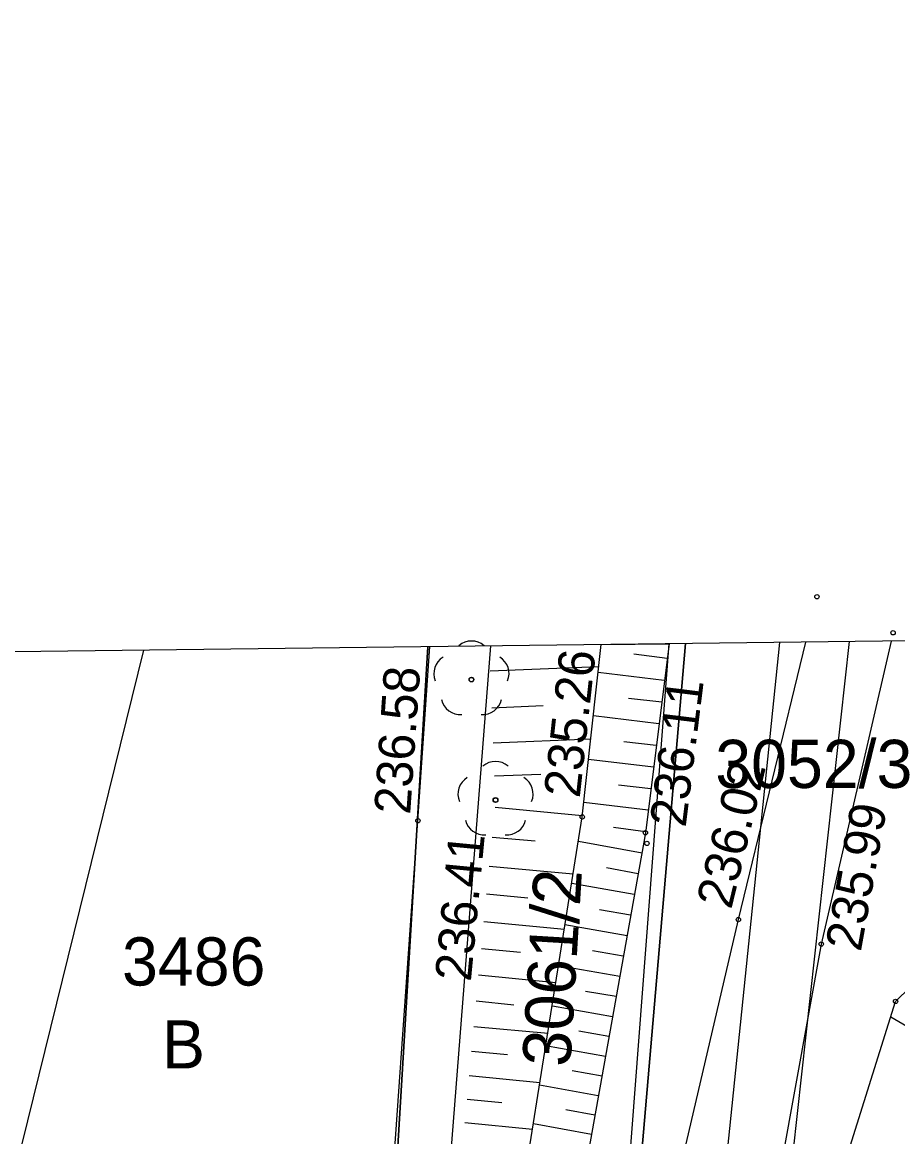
# Model space of a CAD drawing. Extents: x 6596400 to 6597200, y 5539751 to 5540251.
# Drawn here: x 6596707.49 to 6596725.66, y 5540110.79 to 5540133.92 of the extents above; entities that cross this region are included whole.
import ezdxf

# ---------------------------------------------------------------- set-up
doc = ezdxf.new("R2010")
doc.units = 0
for name, color, linetype in [('000 Inne (niezydentyfikowane)', 7, 'Continuous'), ('140-Punkty robocze', 7, 'Continuous'), ('210-oznaczenie konturu użytku gruntowego', 7, 'Continuous'), ('211-numer działki ewidencyjnej', 7, 'Continuous'), ('218-kontur użytku gruntowego', 7, 'Continuous'), ('219-działka ewidencyjna', 7, 'Continuous'), ('drzewo liściaste', 7, 'Continuous'), ('jezdnia', 7, 'Continuous'), ('Linia obszaru zagospodarowania terenu', 7, 'Continuous'), ('ogrodzenie trwałe', 7, 'Continuous'), ('pikieta sztuczna', 7, 'Continuous'), ('pikieta sztuczna-Atr2', 7, 'Continuous'), ('przewód kanalizacyjny', 7, 'Continuous'), ('skarpa nieumocniona', 7, 'Continuous'), ('Strefa korytarza ekologicznego', 7, 'Continuous'), ('Zakres', 7, 'Continuous')]:
    doc.layers.add(name, color=color, linetype=linetype)

# ---------------------------------------------------------------- blocks, each defined once
blk = doc.blocks.new('OP021')
blk.add_circle((0, 0), 0.05)
for centre, start, end in [((0, 0.4), 49.272, 130.728), ((-0.38, 0.124), 121.308, 202.548), ((0.38, 0.124), 337.452, 58.692), ((-0.235, -0.324), 193.221, 274.871), ((0.235, -0.324), 265.129, 346.779)]:
    blk.add_arc(centre, 0.4, start, end)
blk = doc.blocks.new('PIKIETA')
blk.add_circle((0, 0), 0.045)
blk = doc.blocks.new('PW01')
blk.add_circle((0, 0), 0.045)

msp = doc.modelspace()

# ---------------------------------------------------------------- linework, layer by layer
at = {"layer": '000 Inne (niezydentyfikowane)'}
for p, q in [((6596720.87, 5540120.72), (6596720.18, 5540120.81)), ((6596717.2, 5540120.46), (6596719.45, 5540120.55)), ((6596720.81, 5540120.26), (6596719.44, 5540120.43)), ((6596720.76, 5540119.81), (6596720.07, 5540119.89)), ((6596717.23, 5540119.69), (6596718.3, 5540119.74)), ((6596720.7, 5540119.36), (6596719.34, 5540119.53)), ((6596717.26, 5540118.97), (6596719.29, 5540119.05)), ((6596720.64, 5540118.91), (6596719.97, 5540118.99)), ((6596720.59, 5540118.46), (6596719.24, 5540118.62)), ((6596717.29, 5540118.28), (6596718.25, 5540118.32)), ((6596720.53, 5540118.01), (6596719.86, 5540118.09)), ((6596720.48, 5540117.57), (6596719.14, 5540117.73)), ((6596717.3, 5540117.63), (6596719.11, 5540117.46)), ((6596717.24, 5540117.01), (6596718.13, 5540116.93)), ((6596720.42, 5540117.12), (6596719.76, 5540117.21)), ((6596720.35, 5540116.68), (6596719.03, 5540116.92)), ((6596717.18, 5540116.41), (6596718.92, 5540116.25)), ((6596720.27, 5540116.25), (6596719.61, 5540116.37)), ((6596720.19, 5540115.82), (6596718.89, 5540116.05)), ((6596717.12, 5540115.83), (6596717.98, 5540115.75)), ((6596720.11, 5540115.39), (6596719.47, 5540115.5)), ((6596717.07, 5540115.26), (6596718.74, 5540115.1)), ((6596720.04, 5540114.96), (6596718.75, 5540115.19)), ((6596717.02, 5540114.7), (6596717.83, 5540114.62)), ((6596719.96, 5540114.54), (6596719.32, 5540114.65)), ((6596719.89, 5540114.12), (6596718.62, 5540114.34)), ((6596716.96, 5540114.15), (6596718.56, 5540113.99)), ((6596719.81, 5540113.7), (6596719.18, 5540113.81)), ((6596716.91, 5540113.61), (6596717.69, 5540113.53)), ((6596719.74, 5540113.28), (6596718.49, 5540113.5)), ((6596716.86, 5540113.08), (6596718.4, 5540112.94)), ((6596725.51, 5540113.28), (6596729.8, 5540110.8)), ((6596719.66, 5540112.87), (6596719.04, 5540112.98)), ((6596719.59, 5540112.46), (6596718.35, 5540112.68)), ((6596716.81, 5540112.57), (6596717.56, 5540112.5)), ((6596719.52, 5540112.05), (6596718.9, 5540112.16)), ((6596716.76, 5540112.06), (6596718.23, 5540111.92)), ((6596719.44, 5540111.64), (6596718.22, 5540111.86)), ((6596716.72, 5540111.57), (6596717.44, 5540111.5)), ((6596719.37, 5540111.24), (6596718.77, 5540111.35)), ((6596716.67, 5540111.09), (6596718.08, 5540110.95)), ((6596719.3, 5540110.84), (6596718.1, 5540111.06))]:
    msp.add_line(p, q, dxfattribs=at)
at = {"layer": '218-kontur użytku gruntowego'}
for points in [[(6596714.65, 5540099.99), (6596715.907, 5540120.962)], [(6596715.907, 5540120.962), (6596714.65, 5540099.99)], [(6596721.251, 5540121.028), (6596719.42, 5540099.7)], [(6596719.42, 5540099.7), (6596721.251, 5540121.028)]]:
    msp.add_lwpolyline(points, dxfattribs=at)
at = {"layer": '219-działka ewidencyjna'}
for points in [[(6596714.65, 5540099.99), (6596715.907, 5540120.962)], [(6596719.42, 5540099.7), (6596721.251, 5540121.028)]]:
    msp.add_lwpolyline(points, dxfattribs=at)
at = {"layer": 'jezdnia'}
for points in [[(6596725.521, 5540121.08), (6596724.07, 5540114.79), (6596723.26, 5540110.33), (6596723.1, 5540103.54), (6596722.97, 5540100.28), (6596722.67, 5540097.08), (6596723.35, 5540095.14), (6596720.92, 5540095.72), (6596718.03, 5540096.54)], [(6596718.03, 5540096.54), (6596719.7, 5540098.47), (6596721, 5540103.83), (6596721.22, 5540110.44), (6596722.35, 5540115.3), (6596723.751, 5540121.058)]]:
    msp.add_lwpolyline(points, dxfattribs=at)
at = {"layer": 'Linia obszaru zagospodarowania terenu'}
for points in [[(6596717.208, 5540120.978), (6596716.13, 5540107.22), (6596715.39, 5540091.82)], [(6596718.63, 5540088.53), (6596719.66, 5540104.62), (6596720.915, 5540121.024)]]:
    msp.add_lwpolyline(points, dxfattribs=at)
at = {"layer": 'ogrodzenie trwałe'}
msp.add_lwpolyline([(6596714.61, 5540101.89), (6596715.7, 5540117.35), (6596715.95, 5540120.963)], dxfattribs=at)
at = {"layer": 'przewód kanalizacyjny'}
for points in [[(6596723.203, 5540121.052), (6596721.45, 5540104.04), (6596720.5, 5540082.91), (6596720.2, 5540067.11), (6596715.44, 5540062.371)], [(6596724.65, 5540121.069), (6596722.94, 5540105.56), (6596720.82, 5540067.29), (6596715.895, 5540061.995)]]:
    msp.add_lwpolyline(points, dxfattribs=at)
at = {"layer": 'skarpa nieumocniona'}
for points in [[(6596751.79, 5540118.27), (6596760.37, 5540114.69), (6596748.71, 5540116.3), (6596743.9, 5540116.21), (6596740.41, 5540117.83), (6596735.6, 5540111.55), (6596736.12, 5540109.87), (6596735.55, 5540098.25), (6596728.64, 5540097.09), (6596724.81, 5540103.41), (6596724.02, 5540108.52), (6596725.61, 5540113.6), (6596728.6, 5540116.52), (6596734.94, 5540121.2), (6596745.21, 5540121.32)], [(6596751.79, 5540118.27), (6596760.37, 5540114.69), (6596748.71, 5540116.3), (6596743.9, 5540116.21), (6596740.41, 5540117.83), (6596735.6, 5540111.55), (6596736.12, 5540109.87), (6596735.55, 5540098.25), (6596728.64, 5540097.09), (6596724.81, 5540103.41), (6596724.02, 5540108.52), (6596725.61, 5540113.6), (6596728.6, 5540116.52), (6596734.94, 5540121.2), (6596745.21, 5540121.32)], [(6596720.42, 5540117.1), (6596718.24, 5540104.93), (6596717.23, 5540099.21), (6596716.31, 5540100.14), (6596717.18, 5540105.3), (6596719.11, 5540117.43), (6596719.5, 5540121.01), (6596720.91, 5540121.02)], [(6596720.42, 5540117.1), (6596718.24, 5540104.93), (6596717.23, 5540099.21), (6596716.31, 5540100.14), (6596717.18, 5540105.3), (6596719.11, 5540117.43), (6596719.5, 5540121.01), (6596720.91, 5540121.02)]]:
    msp.add_lwpolyline(points, close=True, dxfattribs=at)
at = {"layer": 'Strefa korytarza ekologicznego'}
msp.add_lwpolyline([(6596698.383, 5540076.46), (6596706.03, 5540104.75), (6596710.01, 5540120.89)], dxfattribs=at)
at = {"layer": 'Zakres'}
msp.add_lwpolyline([(6596822.22, 5540097.5), (6596800.39, 5540105.4), (6596755.76, 5540121.45), (6596697.73, 5540120.74), (6596659.35, 5540133.92), (6596647.64, 5540109.28), (6596697.73, 5540077), (6596721.01, 5540057.77), (6596727.72, 5540045.95), (6596731.95, 5540033.61), (6596741.17, 5540031.18), (6596755.59, 5540029.2), (6596757.85, 5540044.22), (6596787.25, 5540055.04), (6596806.3, 5540048.33), (6596813.97, 5540042.6), (6596833.15, 5540068.58), (6596822.3, 5540077.75)], close=True, dxfattribs=at)

# ---------------------------------------------------------------- block references
at = {"layer": '140-Punkty robocze'}
for p in [(6596723.98, 5540122), (6596725.56, 5540121.25), (6596716.81, 5540120.28), (6596717.31, 5540117.78), (6596719.11, 5540117.43), (6596715.7, 5540117.35), (6596720.42, 5540117.1), (6596720.45, 5540116.88), (6596722.35, 5540115.3), (6596724.07, 5540114.79), (6596725.61, 5540113.6)]:
    msp.add_blockref('PIKIETA', p, dxfattribs=at)
at = {"layer": 'drzewo liściaste'}
for p in [(6596716.81, 5540120.28), (6596717.31, 5540117.78)]:
    msp.add_blockref('OP021', p, dxfattribs=at)
at = {"layer": 'pikieta sztuczna'}
for p in [(6596717.31, 5540117.78), (6596719.11, 5540117.43), (6596715.7, 5540117.35), (6596720.42, 5540117.1), (6596722.35, 5540115.3), (6596724.07, 5540114.79), (6596725.61, 5540113.6)]:
    msp.add_blockref('PW01', p, dxfattribs=at)

# ---------------------------------------------------------------- texts
at = {"layer": '210-oznaczenie konturu użytku gruntowego'}
msp.add_text('B', height=1, dxfattribs=at).set_placement((6596710.39, 5540112.21))
at = {"layer": '211-numer działki ewidencyjnej'}
for s, p in [('3052/3', (6596721.87, 5540118.03)), ('3486', (6596709.56, 5540113.93))]:
    msp.add_text(s, height=1, dxfattribs=at).set_placement(p)
msp.add_text('3061/2', height=1, rotation=86.57, dxfattribs=at).set_placement((6596718.86, 5540112.23))
at = {"layer": 'pikieta sztuczna-Atr2'}
for s, rotation, p in [('235.26', 83.757, (6596719.056, 5540117.808)), ('236.58', 86.046, (6596715.538, 5540117.468)), ('236.11', 82.942, (6596721.254, 5540117.198)), ('236.02', 76.327, (6596722.199, 5540115.493)), ('235.99', 79.706, (6596724.888, 5540114.616)), ('236.41', 84.54, (6596716.797, 5540113.999))]:
    msp.add_text(s, height=0.75, rotation=rotation, dxfattribs=at).set_placement(p)

doc.saveas('drawing.dxf')
